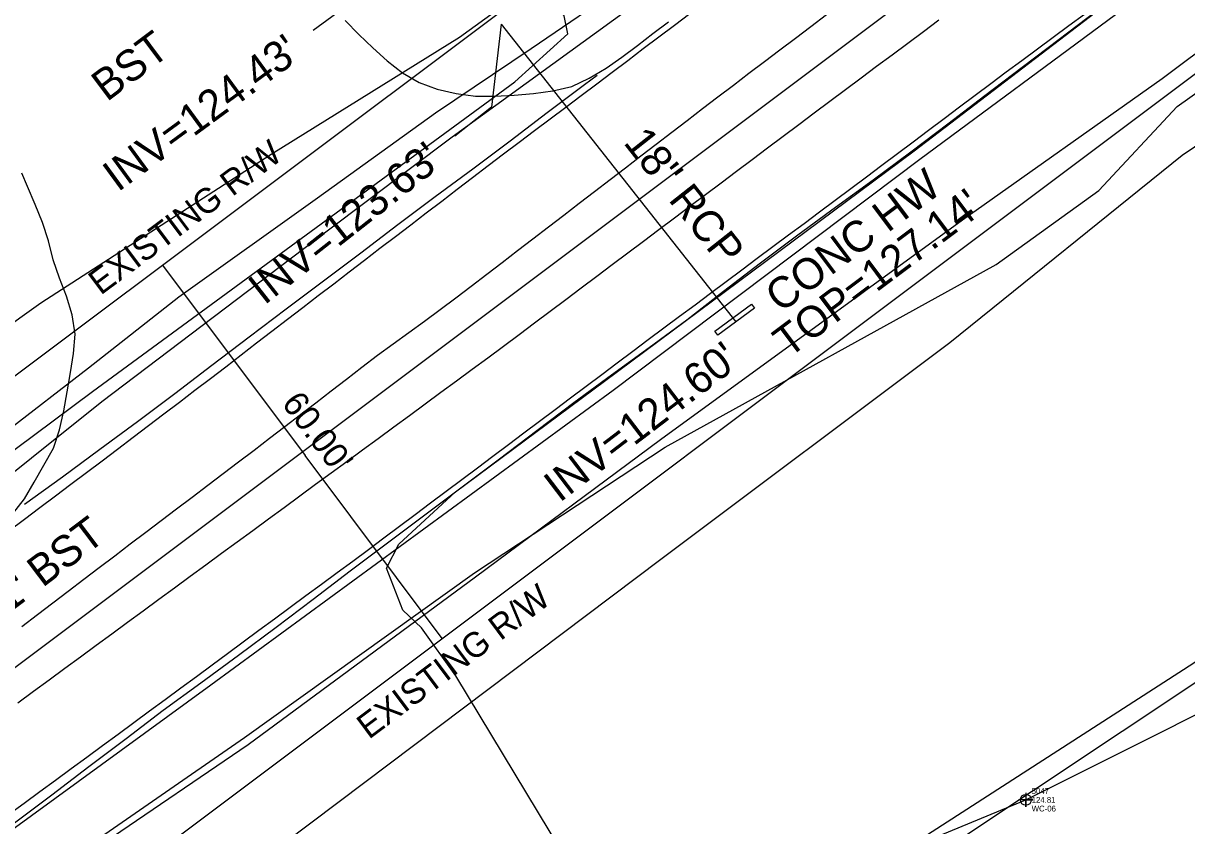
# Model space of a CAD drawing. Extents: x 2186615 to 2188822, y 629899 to 631820.
# Drawn here: x 2188154.1 to 2188303.7, y 631119.9 to 631223.1 of the extents above; entities that cross this region are included whole.
import ezdxf

# ---------------------------------------------------------------- set-up
doc = ezdxf.new("R2010")
doc.units = 0
for name, color, linetype in [('Exist Environmental Wetland Boundary', 7, 'Continuous'), ('Exist Environmental Wetland Boundary Cogo Comment', 7, 'Continuous'), ('Exist Environmental Wetland Boundary Cogo Elevation', 7, 'Continuous'), ('Exist Environmental Wetland Boundary Cogo Number', 7, 'Continuous'), ('Exist Environmental Wetland Boundary Cogo Point CELL', 7, 'Continuous'), ('Exist Horizontal Alignment', 7, 'Continuous'), ('Exist Right of Way Line', 7, 'Continuous'), ('Exist Right of Way Line Text', 7, 'Continuous'), ('Exist Right of Way Width CELL', 7, 'Continuous'), ('Exist Roads EOP', 7, 'Continuous'), ('Exist Roads EOP Text', 7, 'Continuous'), ('Exist Roads EOT', 7, 'Continuous'), ('Exist Structure Minor Head and End Wall', 7, 'Continuous'), ('Exist Structure Minor Head and End Wall Text', 7, 'Continuous'), ('Exist Structure Minor Pipes HDPE 15 Inch Invert', 7, 'Continuous'), ('Exist Structure Minor Pipes HDPE 15 Inch Leader', 7, 'Continuous'), ('Exist Structure Minor Pipes RCP 18 Inch', 7, 'Continuous'), ('Exist Structure Minor Pipes RCP 18 Inch Invert', 7, 'Continuous'), ('Exist Structure Minor Pipes RCP 18 Inch Leader', 7, 'Continuous'), ('Exist Structure Minor Pipes RCP 18 Inch Text', 7, 'Continuous'), ('Exist Utilities Gas UG Line SUE LOS B', 7, 'Continuous'), ('Exist Utilities Sanitary Sewer Forced Main SUE LOS B', 7, 'Continuous'), ('Exist Utilities Telephone UG Cable SUE LOS C', 7, 'Continuous'), ('Exist Utilities Telephone UG FO SUE LOS B', 7, 'Continuous'), ('Exist Utilities Water UG Line SUE LOS B', 7, 'Continuous'), ('Exist Vegetation Woods Line', 7, 'Continuous')]:
    doc.layers.add(name, color=color, linetype=linetype)

msp = doc.modelspace()

# ---------------------------------------------------------------- linework, layer by layer
at = {"layer": 'Exist Environmental Wetland Boundary'}
msp.add_lwpolyline([(2188215.58, 631076.01), (2188215.79, 631088.55), (2188241.59, 631106.05), (2188283.04, 631123.21), (2188321.67, 631142.56)], dxfattribs=at)
at = {"layer": 'Exist Environmental Wetland Boundary Cogo Point CELL'}
msp.add_lwpolyline([(2188283.04, 631124.11), (2188283.04, 631122.31), (2188283.04, 631123.21), (2188283.94, 631123.21), (2188282.14, 631123.21)], dxfattribs=at)
msp.add_circle((2188283.04, 631123.21), 0.703, dxfattribs=at)
at = {"layer": 'Exist Horizontal Alignment'}
msp.add_line((2187136.41, 630378.11), (2188520.86, 631416.04), dxfattribs=at)
at = {"layer": 'Exist Right of Way Line'}
for p, q in [((2187118.41, 630402.11), (2188502.83, 631440.02)), ((2187154.4, 630354.1), (2188538.85, 631392.04)), ((2187850.54, 630836.34), (2188624.63, 631350.85)), ((2187850.54, 630836.34), (2188371.34, 631182.5)), ((2187850.54, 630836.34), (2188371.34, 631182.5))]:
    msp.add_line(p, q, dxfattribs=at)
at = {"layer": 'Exist Right of Way Width CELL'}
for p in [(2188171.97, 631191.97), (2188207.96, 631143.97)]:
    msp.add_line(p, (2188190.34, 631167.47), dxfattribs=at)
at = {"layer": 'Exist Roads EOP'}
for points in [[(2188292.13, 631224.61), (2188287.34, 631221), (2188282.55, 631217.39), (2188277.78, 631213.75), (2188273.01, 631210.11), (2188268.23, 631206.48), (2188263.41, 631202.91), (2188258.57, 631199.37), (2188253.72, 631195.82), (2188248.93, 631192.22), (2188244.17, 631188.57), (2188239.42, 631184.9), (2188234.59, 631181.34), (2188229.73, 631177.82), (2188224.91, 631174.25), (2188220.12, 631170.64), (2188215.32, 631167.03), (2188210.52, 631163.43), (2188205.72, 631159.83), (2188200.93, 631156.23), (2188196.14, 631152.61), (2188191.36, 631148.98), (2188186.59, 631145.35), (2188181.78, 631141.77), (2188176.93, 631138.22), (2188172.09, 631134.68), (2188167.31, 631131.06), (2188162.53, 631127.43), (2188157.74, 631123.82), (2188152.94, 631120.21)], [(2188195.49, 631223.43), (2188197.23, 631221.64), (2188199.03, 631219.91), (2188200.88, 631218.24), (2188202.85, 631216.7), (2188205, 631215.44), (2188207.34, 631214.58), (2188209.78, 631214.03), (2188212.25, 631213.71), (2188214.75, 631213.7), (2188217.24, 631213.83), (2188219.73, 631214.04), (2188222.2, 631214.37), (2188224.64, 631214.94), (2188226.89, 631216.02), (2188229.05, 631217.28), (2188231.09, 631218.72), (2188233.09, 631220.22), (2188235.08, 631221.74), (2188237.08, 631223.24)], [(2188154.26, 631161.21), (2188159.11, 631164.75), (2188163.95, 631168.29), (2188168.77, 631171.86), (2188173.56, 631175.48), (2188178.34, 631179.11), (2188183.12, 631182.73), (2188187.91, 631186.35), (2188192.69, 631189.96), (2188197.49, 631193.57), (2188202.28, 631197.18), (2188207.08, 631200.78), (2188211.89, 631204.37), (2188216.69, 631207.97), (2188221.48, 631211.58), (2188226.28, 631215.19), (2188227.89, 631216.4)], [(2188152.69, 631159.94), (2188154.22, 631161.92), (2188155.49, 631164.07), (2188157.96, 631168.42), (2188158.73, 631170.8), (2188159.28, 631173.23), (2188159.74, 631175.69), (2188160.14, 631178.15), (2188160.54, 631180.62), (2188160.74, 631183.11), (2188160.38, 631185.58), (2188159.63, 631187.96), (2188158.76, 631190.31), (2188157.93, 631192.66), (2188157.31, 631195.08), (2188156.56, 631197.46), (2188155.61, 631199.76), (2188154.64, 631202.06), (2188153.9, 631203.78)]]:
    msp.add_lwpolyline(points, dxfattribs=at)
at = {"layer": 'Exist Roads EOT'}
for points in [[(2188290.58, 631224.21), (2188288.57, 631222.72), (2188286.56, 631221.24), (2188284.55, 631219.75), (2188282.54, 631218.26), (2188280.53, 631216.78), (2188278.52, 631215.29), (2188276.52, 631213.79), (2188274.52, 631212.29), (2188272.52, 631210.79), (2188270.52, 631209.29), (2188268.53, 631207.78), (2188266.53, 631206.28), (2188264.53, 631204.78), (2188262.53, 631203.28), (2188260.53, 631201.78), (2188258.53, 631200.28), (2188256.52, 631198.79), (2188254.52, 631197.29), (2188252.51, 631195.8), (2188250.51, 631194.31), (2188248.5, 631192.81), (2188246.5, 631191.32), (2188244.5, 631189.83), (2188242.49, 631188.33), (2188240.49, 631186.84), (2188238.48, 631185.34), (2188236.48, 631183.85), (2188234.47, 631182.35), (2188232.48, 631180.85), (2188230.48, 631179.35), (2188228.48, 631177.85), (2188226.48, 631176.35), (2188224.48, 631174.85), (2188222.48, 631173.35), (2188220.48, 631171.84), (2188218.48, 631170.34), (2188216.49, 631168.84), (2188214.49, 631167.34), (2188212.49, 631165.84), (2188210.48, 631164.34), (2188208.48, 631162.85), (2188206.48, 631161.35), (2188204.48, 631159.85), (2188202.48, 631158.36), (2188200.47, 631156.86), (2188198.47, 631155.36), (2188196.46, 631153.87), (2188194.45, 631152.38), (2188192.44, 631150.9), (2188190.43, 631149.42), (2188188.42, 631147.93), (2188186.41, 631146.45), (2188184.39, 631144.97), (2188182.38, 631143.48), (2188180.37, 631142), (2188178.36, 631140.51), (2188176.35, 631139.03), (2188174.33, 631137.55), (2188172.32, 631136.07), (2188170.3, 631134.59), (2188168.29, 631133.11), (2188166.28, 631131.62), (2188164.26, 631130.14), (2188162.25, 631128.66), (2188160.23, 631127.18), (2188158.22, 631125.7), (2188156.2, 631124.22), (2188154.19, 631122.74), (2188152.17, 631121.26)], [(2188152.23, 631157.78), (2188154.23, 631159.29), (2188156.22, 631160.79), (2188158.22, 631162.29), (2188160.22, 631163.8), (2188162.21, 631165.31), (2188164.21, 631166.81), (2188166.2, 631168.32), (2188168.2, 631169.83), (2188170.19, 631171.33), (2188172.18, 631172.84), (2188174.17, 631174.36), (2188176.16, 631175.87), (2188178.15, 631177.39), (2188180.13, 631178.91), (2188182.11, 631180.44), (2188184.09, 631181.97), (2188186.07, 631183.49), (2188188.05, 631185.01), (2188190.04, 631186.53), (2188192.02, 631188.05), (2188194.01, 631189.57), (2188195.99, 631191.09), (2188197.98, 631192.61), (2188199.96, 631194.13), (2188201.95, 631195.65), (2188203.93, 631197.17), (2188205.92, 631198.69), (2188207.9, 631200.21), (2188209.89, 631201.73), (2188211.87, 631203.25), (2188213.87, 631204.76), (2188215.86, 631206.27), (2188217.86, 631207.77), (2188219.85, 631209.28), (2188221.85, 631210.78), (2188223.85, 631212.28), (2188225.85, 631213.79), (2188227.84, 631215.29), (2188229.84, 631216.8), (2188231.84, 631218.3), (2188233.83, 631219.81), (2188235.83, 631221.31), (2188237.83, 631222.81), (2188239.82, 631224.32)], [(2188153.37, 631135.69), (2188155.38, 631137.17), (2188157.4, 631138.65), (2188159.41, 631140.12), (2188161.43, 631141.6), (2188163.45, 631143.08), (2188165.46, 631144.56), (2188167.48, 631146.04), (2188169.49, 631147.52), (2188171.51, 631149), (2188173.53, 631150.47), (2188175.54, 631151.95), (2188177.56, 631153.43), (2188179.58, 631154.91), (2188181.59, 631156.39), (2188183.61, 631157.86), (2188185.62, 631159.34), (2188187.64, 631160.82), (2188189.66, 631162.3), (2188191.67, 631163.78), (2188193.69, 631165.25), (2188195.71, 631166.73), (2188197.72, 631168.21), (2188199.74, 631169.69), (2188201.75, 631171.17), (2188203.77, 631172.65), (2188205.78, 631174.13), (2188207.79, 631175.61), (2188209.81, 631177.09), (2188211.82, 631178.58), (2188213.83, 631180.06), (2188215.85, 631181.54), (2188217.85, 631183.03), (2188219.86, 631184.53), (2188221.86, 631186.03), (2188223.85, 631187.53), (2188225.85, 631189.03), (2188227.85, 631190.54), (2188229.85, 631192.04), (2188231.85, 631193.54), (2188233.84, 631195.04), (2188235.84, 631196.54), (2188237.84, 631198.05), (2188239.84, 631199.55), (2188241.84, 631201.05), (2188243.84, 631202.55), (2188245.83, 631204.05), (2188247.83, 631205.56), (2188249.83, 631207.06), (2188251.83, 631208.56), (2188253.83, 631210.06), (2188255.83, 631211.56), (2188257.83, 631213.05), (2188259.84, 631214.55), (2188261.84, 631216.04), (2188263.85, 631217.54), (2188265.85, 631219.03), (2188267.85, 631220.53), (2188269.86, 631222.02), (2188271.86, 631223.52)], [(2188153.91, 631145.51), (2188155.89, 631147.03), (2188157.88, 631148.54), (2188159.87, 631150.06), (2188161.86, 631151.57), (2188163.85, 631153.09), (2188165.84, 631154.6), (2188167.83, 631156.11), (2188169.83, 631157.62), (2188171.82, 631159.13), (2188173.81, 631160.64), (2188175.8, 631162.15), (2188177.8, 631163.66), (2188179.79, 631165.17), (2188181.78, 631166.68), (2188183.77, 631168.19), (2188185.76, 631169.7), (2188187.74, 631171.23), (2188189.73, 631172.75), (2188191.71, 631174.27), (2188193.69, 631175.79), (2188195.67, 631177.32), (2188197.65, 631178.84), (2188199.63, 631180.37), (2188201.64, 631181.86), (2188203.67, 631183.32), (2188205.71, 631184.77), (2188207.72, 631186.25), (2188209.71, 631187.76), (2188211.7, 631189.28), (2188213.69, 631190.79), (2188215.67, 631192.32), (2188217.66, 631193.84), (2188219.64, 631195.36), (2188221.62, 631196.88), (2188223.61, 631198.4), (2188225.59, 631199.92), (2188227.57, 631201.44), (2188229.56, 631202.96), (2188231.54, 631204.49), (2188233.52, 631206.01), (2188235.51, 631207.53), (2188237.49, 631209.05), (2188239.47, 631210.57), (2188241.46, 631212.1), (2188243.44, 631213.61), (2188245.43, 631215.13), (2188247.43, 631216.64), (2188249.42, 631218.15), (2188251.41, 631219.65), (2188253.41, 631221.16), (2188255.4, 631222.67), (2188257.39, 631224.18)]]:
    msp.add_lwpolyline(points, dxfattribs=at)
at = {"layer": 'Exist Structure Minor Head and End Wall'}
msp.add_lwpolyline([(2188248.14, 631186.42), (2188243.42, 631182.94), (2188243.03, 631183.47), (2188247.75, 631186.95)], close=True, dxfattribs=at)
at = {"layer": 'Exist Structure Minor Pipes HDPE 15 Inch Leader'}
msp.add_lwpolyline([(2188206.55, 631228.73), (2188196.19, 631225.67), (2188191.35, 631222.13)], dxfattribs=at)
at = {"layer": 'Exist Structure Minor Pipes RCP 18 Inch'}
msp.add_line((2188215.54, 631222.95), (2188245.75, 631184.67), dxfattribs=at)
at = {"layer": 'Exist Structure Minor Pipes RCP 18 Inch Leader'}
msp.add_lwpolyline([(2188215.54, 631222.95), (2188214.3, 631212.28), (2188209.58, 631208.57)], dxfattribs=at)
at = {"layer": 'Exist Utilities Gas UG Line SUE LOS B'}
msp.add_lwpolyline([(2188051.96, 631102.7), (2188059.93, 631108.6), (2188070.82, 631114.33), (2188080.3, 631119.13), (2188092.02, 631126.53), (2188100.57, 631133.33), (2188111.14, 631140.34), (2188124.97, 631149.64), (2188137.6, 631159.99), (2188151.69, 631170.44), (2188162.45, 631178.77), (2188174.08, 631187.88), (2188191.92, 631200.6), (2188207.11, 631211.57), (2188219.39, 631219.84), (2188231.62, 631228.2)], dxfattribs=at)
at = {"layer": 'Exist Utilities Sanitary Sewer Forced Main SUE LOS B'}
msp.add_lwpolyline([(2188052.08, 631035.89), (2188074.5, 631052.61), (2188093.79, 631066.37), (2188121.43, 631086.62), (2188146.17, 631105.29), (2188183, 631130.32), (2188212.25, 631151.9), (2188236.06, 631169.55), (2188274.9, 631197.79), (2188300.59, 631215.98), (2188344.72, 631249.04), (2188387.13, 631281.33), (2188437.44, 631319.58), (2188480.75, 631351.94), (2188530.77, 631388.8), (2188537.37, 631394.07)], dxfattribs=at)
at = {"layer": 'Exist Utilities Telephone UG Cable SUE LOS C'}
for points in [[(2188096.88, 630993.34), (2188080.22, 631017.51), (2188064.37, 631042.87), (2188062.98, 631045.24), (2188062.65, 631047.71), (2188067.09, 631054.3), (2188068.63, 631056.84), (2188089.09, 631072.74), (2188116.44, 631092.81), (2188141.03, 631110.94), (2188178.22, 631138.01), (2188229.96, 631175.9), (2188269.4, 631205.59), (2188294.58, 631224.2), (2188340.11, 631258.2), (2188382.72, 631289.85), (2188432.93, 631327.36), (2188477.32, 631360.56), (2188524.82, 631398.08), (2188530.94, 631402.62)], [(2188239.88, 631089.23), (2188209.7, 631139.17), (2188205.31, 631145.33), (2188202.92, 631147.6), (2188200.81, 631153.01), (2188202.37, 631156.1), (2188209.69, 631162.82), (2188228.85, 631177.06), (2188268.68, 631206.68), (2188293.54, 631225.66), (2188339.11, 631259.48), (2188381.57, 631291.6), (2188431.82, 631329.3), (2188475.74, 631362.76), (2188523.99, 631399.21), (2188530.06, 631403.8)], [(2188094.37, 630991.41), (2188096.88, 630993.34), (2188087.79, 631026.43), (2188086.82, 631054.16), (2188087.06, 631058.84), (2188088.93, 631062.35), (2188093.27, 631066.84), (2188121.22, 631086.85), (2188145.88, 631105.9), (2188182.55, 631131.21), (2188212.13, 631152.41), (2188236.63, 631168.55), (2188279.23, 631192.06), (2188292.43, 631201.57), (2188302.49, 631212.36), (2188347.67, 631244.49), (2188388.98, 631278.39), (2188439.32, 631316.4), (2188482.92, 631349.33), (2188532.32, 631387.1), (2188539.16, 631391.7)], [(2188096.88, 630993.34), (2188079.83, 631025.19), (2188068.51, 631044.39), (2188061.79, 631053.43), (2188045.22, 631077.41), (2188041.6, 631082.29), (2188043.38, 631085.49), (2188063.96, 631101.13), (2188102.69, 631130.96), (2188125.87, 631148.05), (2188163, 631175.72), (2188217.3, 631215.55), (2188224.13, 631221.73), (2188223.64, 631224.04), (2188219.58, 631228.63), (2188214.19, 631233.71)]]:
    msp.add_lwpolyline(points, dxfattribs=at)
at = {"layer": 'Exist Utilities Telephone UG FO SUE LOS B'}
msp.add_lwpolyline([(2187859.07, 630951.55), (2187882.76, 630968.07), (2187903.06, 630983.05), (2187928.09, 631001.38), (2187948.02, 631018.93), (2187983.82, 631042.28), (2188016.23, 631068.08), (2188049.6, 631091.76), (2188063.06, 631102.31), (2188071.06, 631108.58), (2188069.02, 631112.49), (2188069.37, 631119.05), (2188075.07, 631125.87), (2188092.55, 631139.53), (2188117.88, 631159.65), (2188156.33, 631187.11), (2188185.96, 631206.22), (2188210.21, 631221.29), (2188233.48, 631238.15), (2188251.53, 631251.3), (2188274.73, 631269.24), (2188303.07, 631290.83)], dxfattribs=at)
at = {"layer": 'Exist Utilities Water UG Line SUE LOS B'}
msp.add_lwpolyline([(2187858.58, 630939.62), (2187877.52, 630954.54), (2187897.98, 630970.72), (2187926.28, 630993.39), (2187953.07, 631014.11), (2187986.18, 631039.09), (2188018.97, 631064.16), (2188052.07, 631088.62), (2188105.21, 631128.41), (2188127.75, 631145.3), (2188164.18, 631174.44), (2188192.98, 631196.26), (2188209.23, 631208.45), (2188231.7, 631224.75), (2188257.48, 631242.51), (2188270.74, 631252.18), (2188280.66, 631259.06), (2188311.2, 631281.93)], dxfattribs=at)
at = {"layer": 'Exist Vegetation Woods Line'}
for points in [[(2187900, 630901.47), (2187930.95, 630926.02), (2187966.57, 630951.75), (2187999.62, 630976.07), (2188035.07, 631001.76), (2188066.4, 631024.95), (2188104.74, 631054.06), (2188133.99, 631077.57), (2188163.27, 631099.35), (2188198, 631125.47), (2188236.07, 631154.15), (2188273.27, 631182), (2188303.14, 631206.11), (2188341.9, 631232.33), (2188374.15, 631253.71), (2188405.25, 631276.99)], [(2188336.81, 631162.74), (2188304.67, 631140.79), (2188253.49, 631107.84), (2188202.91, 631074.1), (2188139.41, 631031.67), (2188093.1, 631000.83), (2188032.1, 630960.3), (2187970.81, 630919.03), (2187899.6, 630870.56), (2187878.91, 630858.57), (2187866.57, 630849.5), (2187856.84, 630841.46), (2187846.68, 630832.19), (2187829.94, 630827.76), (2187807.52, 630819.83), (2187838.54, 630838.9), (2187846.29, 630845.15), (2187849.33, 630854.22), (2187863.66, 630870.01), (2187881.14, 630887.73), (2187900, 630901.47)]]:
    msp.add_lwpolyline(points, dxfattribs=at)

# ---------------------------------------------------------------- texts
at = {"layer": 'Exist Environmental Wetland Boundary Cogo Comment'}
msp.add_text('WC-06', height=0.75, dxfattribs=at).set_placement((2188283.79, 631121.71))
at = {"layer": 'Exist Environmental Wetland Boundary Cogo Elevation'}
msp.add_text('124.81', height=0.75, dxfattribs=at).set_placement((2188283.79, 631122.83))
at = {"layer": 'Exist Environmental Wetland Boundary Cogo Number'}
msp.add_text('5047', height=0.75, dxfattribs=at).set_placement((2188283.79, 631123.96))
at = {"layer": 'Exist Right of Way Line Text'}
for p in [(2188164.03, 631188.02), (2188198.54, 631130.91)]:
    msp.add_text('EXISTING R/W', height=3.2, rotation=36.8593, dxfattribs=at).set_placement(p)
at = {"layer": 'Exist Right of Way Width CELL'}
msp.add_text("60.00'", height=3.2, rotation=306.8593, dxfattribs=at).set_placement((2188187.22, 631174.17))
at = {"layer": 'Exist Roads EOP Text'}
for s, rotation, p in [('BST', 36.8593, (2188164.83, 631212.9)), ("US 301/NC 96/S BRIGHTLEAF BLVD 31' BST", 37.1238, (2188076.81, 631090.07))]:
    msp.add_text(s, height=4, rotation=rotation, dxfattribs=at).set_placement(p)
at = {"layer": 'Exist Structure Minor Head and End Wall Text'}
for s, p in [('CONC HW', (2188251.49, 631185.73)), ("TOP=127.14'", (2188252.52, 631179.94))]:
    msp.add_text(s, height=4, rotation=36.8593, dxfattribs=at).set_placement(p)
at = {"layer": 'Exist Structure Minor Pipes HDPE 15 Inch Invert'}
msp.add_text("INV=124.43'", height=4, rotation=36.1773, dxfattribs=at).set_placement((2188166.25, 631201.3))
at = {"layer": 'Exist Structure Minor Pipes RCP 18 Inch Invert'}
for s, rotation, p in [("INV=123.63'", 38.2092, (2188185.09, 631186.75)), ("INV=124.60'", 37.3233, (2188223.06, 631161.36))]:
    msp.add_text(s, height=4, rotation=rotation, dxfattribs=at).set_placement(p)
at = {"layer": 'Exist Structure Minor Pipes RCP 18 Inch Text'}
msp.add_text('18" RCP', height=4, rotation=308.2798, dxfattribs=at).set_placement((2188231.18, 631207.7))

doc.saveas('drawing.dxf')
